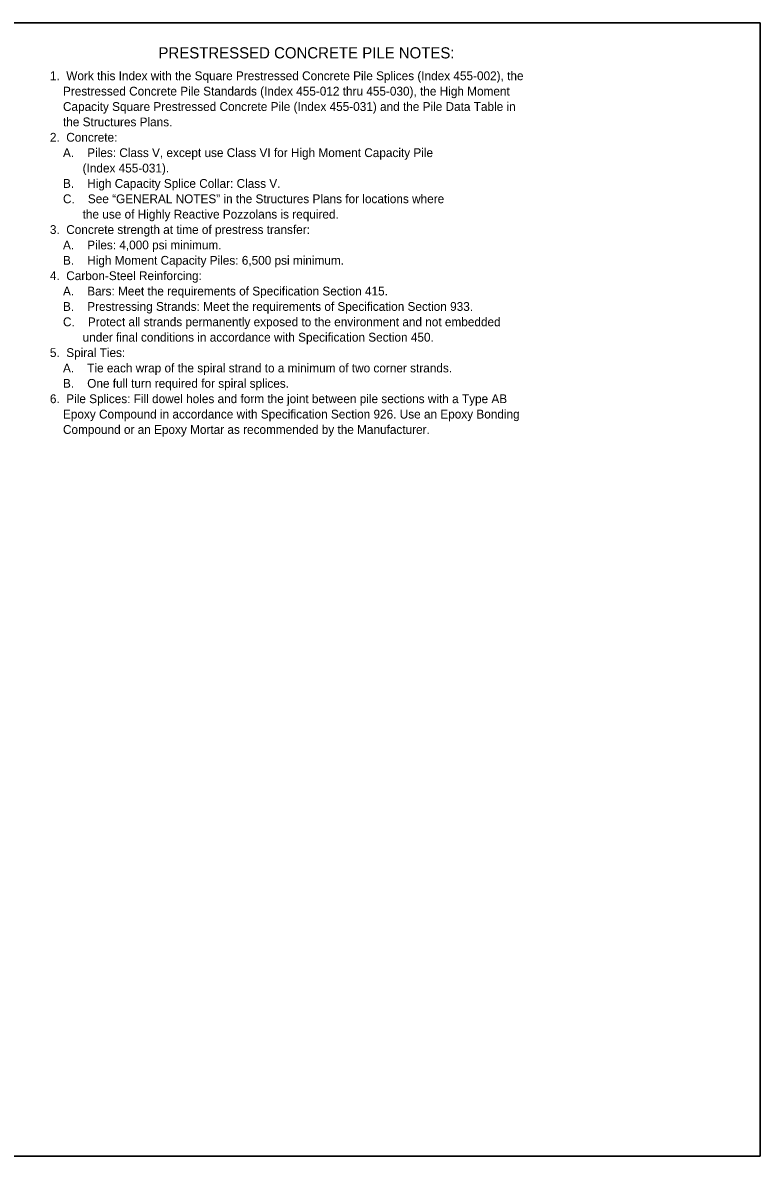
# Model space of a CAD drawing. Extents: x 0 to 20.5, y 0 to 13.
# Drawn here: x 12.09 to 20.53, y 0 to 12.97 of the extents above; entities that cross this region are included whole.
import ezdxf

# ---------------------------------------------------------------- set-up
doc = ezdxf.new("R2010")
doc.units = 0
for name, color, linetype in [('ActivePts-ConstElements', 7, 'Continuous'), ('Dimension', 7, 'Continuous'), ('Miscellaneous1', 7, 'Continuous'), ('PlotBorder_dp', 7, 'Continuous'), ('TextStructures', 7, 'Continuous')]:
    doc.layers.add(name, color=color, linetype=linetype)

msp = doc.modelspace()

# ---------------------------------------------------------------- linework, layer by layer
at = {"layer": 'ActivePts-ConstElements'}
msp.add_lwpolyline([(0, 0), (20.525, 0), (20.525, 12.973), (0, 12.973)], close=True, dxfattribs=at)
at = {"layer": 'Miscellaneous1'}
msp.add_lwpolyline([(0, 12.973), (20.525, 12.973), (20.525, 0), (0, 0)], close=True, dxfattribs=at)
at = {"layer": 'PlotBorder_dp'}
msp.add_line((20.525, 12.973), (20.525, 12.973), dxfattribs=at)

# ---------------------------------------------------------------- texts
at = {"layer": 'Dimension'}
for s, p in [('1.  Work this Index with the Square Prestressed Concrete Pile Splices (Index 455-002), the ', (12.4, 12.315)), ('    Prestressed Concrete Pile Standards (Index 455-012 thru 455-030), the High Moment', (12.4, 12.139)), ('    Capacity Square Prestressed Concrete Pile (Index 455-031) and the Pile Data Table in', (12.4, 11.963)), ('    the Structures Plans.', (12.4, 11.787)), ('2.  Concrete: ', (12.4, 11.611)), ('    A.    Piles: Class V, except use Class VI for High Moment Capacity Pile', (12.4, 11.435)), ('          (Index 455-031). ', (12.4, 11.259)), ('    B.    High Capacity Splice Collar: Class V.', (12.4, 11.083)), ('    C.    See “GENERAL NOTES” in the Structures Plans for locations where', (12.4, 10.907)), ('          the use of Highly Reactive Pozzolans is required.', (12.4, 10.731)), ('3.  Concrete strength at time of prestress transfer:', (12.4, 10.555)), ('    A.    Piles: 4,000 psi minimum.', (12.4, 10.379)), ('    B.    High Moment Capacity Piles: 6,500 psi minimum.', (12.4, 10.203)), ('4.  Carbon-Steel Reinforcing:  ', (12.4, 10.027)), ('    A.    Bars: Meet the requirements of Specification Section 415.', (12.4, 9.851)), ('    B.    Prestressing Strands: Meet the requirements of Specification Section 933.', (12.4, 9.675)), ('    C.    Protect all strands permanently exposed to the environment and not embedded', (12.4, 9.499)), ('          under final conditions in accordance with Specification Section 450.', (12.4, 9.323)), ('5.  Spiral Ties:', (12.4, 9.147)), ('    A.    Tie each wrap of the spiral strand to a minimum of two corner strands.  ', (12.4, 8.971)), ('    B.    One full turn required for spiral splices.', (12.4, 8.795)), ('6.  Pile Splices: Fill dowel holes and form the joint between pile sections with a Type AB', (12.4, 8.619)), ('    Epoxy Compound in accordance with Specification Section 926. Use an Epoxy Bonding', (12.4, 8.443)), ('    Compound or an Epoxy Mortar as recommended by the Manufacturer.', (12.4, 8.267))]:
    msp.add_text(s, height=0.1008, dxfattribs=at).set_placement(p)
at = {"layer": 'TextStructures'}
msp.add_text('PRESTRESSED CONCRETE PILE NOTES:', height=0.128, dxfattribs=at).set_placement((13.642, 12.564))

doc.saveas('drawing.dxf')
